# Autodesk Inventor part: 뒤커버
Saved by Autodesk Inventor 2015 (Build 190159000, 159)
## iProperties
Created: 2025-08
Part Number: 뒤커버
Material: 일반
Document SubType Name: Modeling
Designer: user
Density: 1 g/cm^3
Appearance: 기본값
Author: jhkim
Creation Date: 2025-08-05
Sending System: Autodesk Inventor 2026
Preprocessor: ST-DEVELOPER v20.1
Author: user
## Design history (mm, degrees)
node "뒤커버1"
node "솔리드1"
node "기준1"
